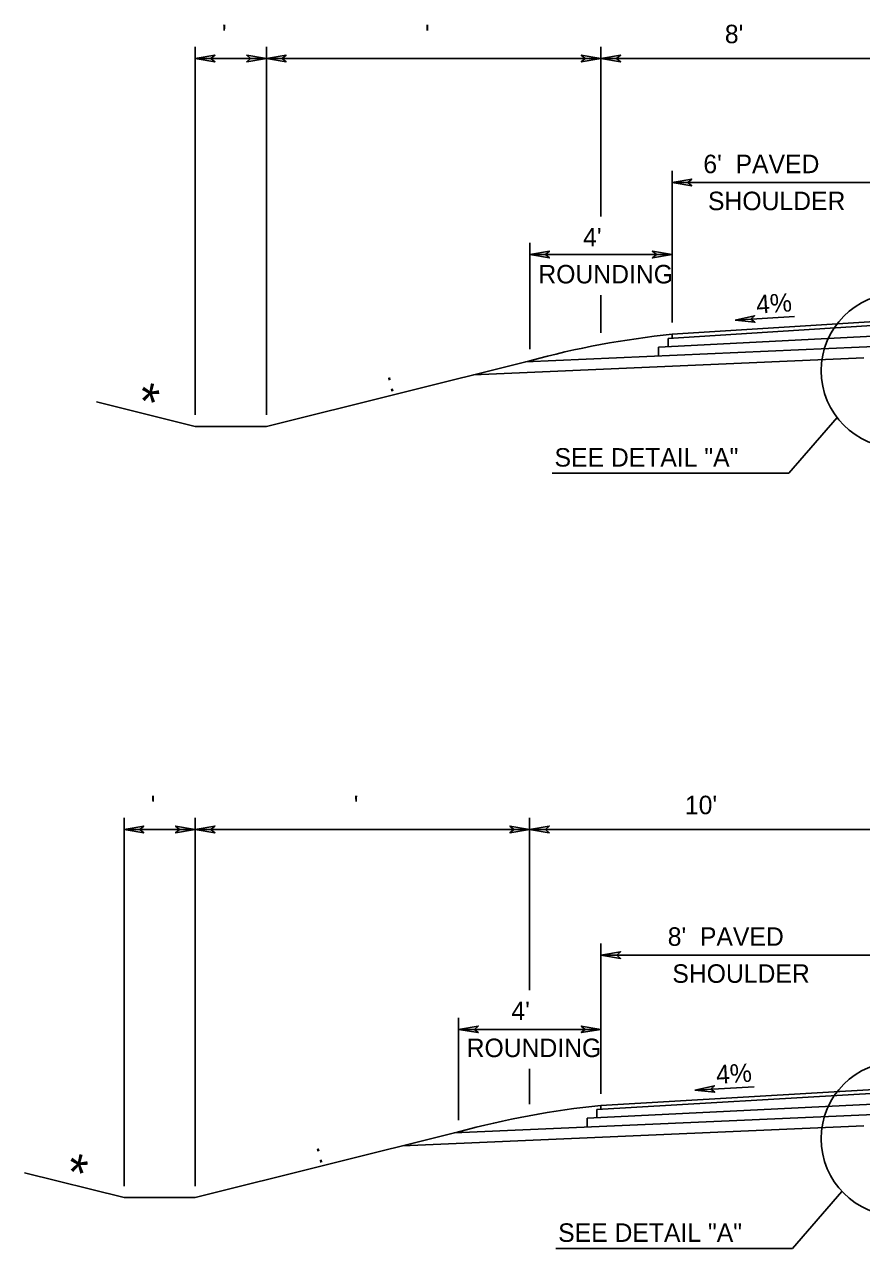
# Model space of a CAD drawing. Extents: x -592 to 1199, y -590 to 416.
# Drawn here: x -138.5 to -75.2, y 57.6 to 150.3 of the extents above; entities that cross this region are included whole.
import ezdxf

# ---------------------------------------------------------------- set-up
doc = ezdxf.new("R2010")
doc.units = 0
doc.layers.add('1', color=7, linetype='Continuous')
doc.layers.add('Des_ Drain_ Ftrs', color=7, linetype='Continuous')

msp = doc.modelspace()

# ---------------------------------------------------------------- linework, layer by layer
at = {"layer": '1'}
for p, q in [((-125.621, 120.711), (-125.621, 148.582)), ((-120.233, 120.711), (-120.233, 148.582)), ((-94.914, 135.731), (-94.914, 148.582)), ((-120.233, 147.702), (-125.621, 147.702)), ((-94.914, 147.702), (-120.233, 147.702)), ((-73.36, 147.702), (-94.914, 147.702)), ((-89.515, 127.705), (-89.515, 139.197)), ((-73.36, 138.317), (-89.515, 138.317)), ((-100.291, 125.696), (-100.291, 133.736)), ((-89.515, 132.856), (-100.291, 132.856)), ((-94.914, 126.926), (-94.914, 129.794)), ((-84.745, 127.887), (-80.256, 128.169)), ((-100.625, 124.733), (-43.725, 127.217)), ((-89.819, 126.506), (-73.6, 127.527)), ((-89.515, 126.825), (-73.365, 127.84)), ((-90.547, 125.857), (-74.304, 126.678)), ((-89.819, 125.894), (-89.819, 126.506)), ((-89.515, 126.525), (-89.515, 126.825)), ((-90.547, 125.173), (-90.547, 125.857)), ((-100.291, 124.816), (-120.233, 119.831)), ((-104.55, 123.751), (-75.007, 125.042)), ((-133.098, 121.7), (-125.621, 119.831)), ((-80.674, 116.3), (-77.026, 120.514)), ((-120.233, 119.831), (-125.621, 119.831)), ((-98.606, 116.3), (-80.674, 116.3)), ((-131.01, 62.338), (-131.01, 90.215)), ((-125.621, 62.338), (-125.621, 90.215)), ((-100.305, 77.171), (-100.305, 90.215)), ((-125.621, 89.335), (-131.01, 89.335)), ((-100.305, 89.335), (-125.621, 89.335)), ((-73.363, 89.335), (-100.305, 89.335)), ((-94.906, 69.324), (-94.906, 80.703)), ((-73.363, 79.823), (-94.906, 79.823)), ((-105.682, 67.315), (-105.682, 75.078)), ((-94.906, 74.198), (-105.682, 74.198)), ((-100.305, 68.545), (-100.305, 71.221)), ((-94.906, 68.444), (-73.368, 69.695)), ((-87.787, 69.601), (-83.296, 69.851)), ((-106.01, 66.353), (-43.728, 69.073)), ((-95.21, 68.126), (-73.602, 69.386)), ((-95.937, 67.478), (-74.306, 68.547)), ((-95.21, 67.514), (-95.21, 68.126)), ((-94.906, 68.143), (-94.906, 68.444)), ((-109.938, 65.373), (-75.01, 66.898)), ((-95.937, 66.793), (-95.937, 67.478)), ((-105.682, 66.435), (-125.621, 61.458)), ((-138.545, 63.342), (-131.01, 61.458)), ((-125.621, 61.458), (-131.01, 61.458)), ((-80.397, 57.607), (-76.658, 61.926)), ((-98.329, 57.607), (-80.397, 57.607))]:
    msp.add_line(p, q, dxfattribs=at)
for centre in [(-72.395, 124.062), (-72.398, 65.918)]:
    msp.add_circle(centre, 5.838, dxfattribs=at)
for centre in [(-82.632, 59.99), (-88.023, 1.609)]:
    msp.add_arc(centre, 67.188, 95.87953, 105.23809, dxfattribs=at)
at = {"layer": 'Des_ Drain_ Ftrs'}
for points in [[(-125.621, 147.702), (-124.133, 147.454), (-124.428, 147.702), (-124.133, 147.951)], [(-120.233, 147.702), (-121.721, 147.454), (-121.426, 147.702), (-121.721, 147.951)], [(-120.233, 147.702), (-118.744, 147.454), (-119.039, 147.702), (-118.744, 147.951)], [(-94.914, 147.702), (-96.402, 147.454), (-96.107, 147.702), (-96.402, 147.951)], [(-94.914, 147.702), (-93.425, 147.454), (-93.72, 147.702), (-93.425, 147.951)], [(-89.515, 138.317), (-88.027, 138.068), (-88.322, 138.317), (-88.027, 138.565)], [(-100.291, 132.856), (-98.803, 132.608), (-99.098, 132.856), (-98.803, 133.104)], [(-89.515, 132.856), (-91.003, 132.608), (-90.708, 132.856), (-91.003, 133.104)], [(-84.745, 127.887), (-83.244, 127.731), (-83.554, 127.961), (-83.275, 128.227)], [(-131.01, 89.335), (-129.522, 89.086), (-129.817, 89.335), (-129.522, 89.583)], [(-125.621, 89.335), (-127.11, 89.086), (-126.815, 89.335), (-127.11, 89.583)], [(-125.621, 89.335), (-124.133, 89.086), (-124.428, 89.335), (-124.133, 89.583)], [(-100.305, 89.335), (-101.793, 89.086), (-101.498, 89.335), (-101.793, 89.583)], [(-100.305, 89.335), (-98.816, 89.086), (-99.111, 89.335), (-98.816, 89.583)], [(-94.906, 79.823), (-93.417, 79.575), (-93.712, 79.823), (-93.417, 80.071)], [(-105.682, 74.198), (-104.194, 73.95), (-104.489, 74.198), (-104.194, 74.447)], [(-94.906, 74.198), (-96.394, 73.95), (-96.099, 74.198), (-96.394, 74.447)], [(-87.787, 69.601), (-86.287, 69.434), (-86.595, 69.666), (-86.314, 69.93)]]:
    msp.add_lwpolyline(points, close=True, dxfattribs=at)

# ---------------------------------------------------------------- texts
at = {"layer": '1'}
for s, p in [(" '", (-124.122, 148.854)), ("  '", (-109.269, 148.854)), ("8'", (-85.527, 148.854)), ("6'  PAVED", (-87.153, 139.017)), ('SHOULDER', (-86.804, 136.217)), ("4'", (-96.255, 133.472)), ('ROUNDING', (-99.644, 130.672)), ('SEE DETAIL "A"', (-98.42, 116.803)), (" '", (-129.511, 90.486)), ("  '", (-114.659, 90.486)), ("10'", (-88.549, 90.486)), ("8'  PAVED", (-89.85, 80.523)), ('SHOULDER', (-89.501, 77.723)), ("4'", (-101.684, 74.898)), ('ROUNDING', (-105.073, 72.098)), ('SEE DETAIL "A"', (-98.144, 58.11))]:
    msp.add_text(s, height=1.4, dxfattribs=at).set_placement(p)
for s, height, rotation, p in [('4%', 1.4, 3.87905, (-83.112, 128.373)), (' : ', 1.4, 14.22821, (-111.442, 122.311)), ('*', 2.8, 347.15207, (-130.186, 120.52)), ('4%', 1.4, 3.46407, (-86.151, 70.076)), (' : ', 1.4, 14.22821, (-116.831, 63.934)), ('*', 2.8, 347.15207, (-135.603, 62.155))]:
    msp.add_text(s, height=height, rotation=rotation, dxfattribs=at).set_placement(p)

doc.saveas('drawing.dxf')
